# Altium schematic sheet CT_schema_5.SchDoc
size 339 x 183 mm
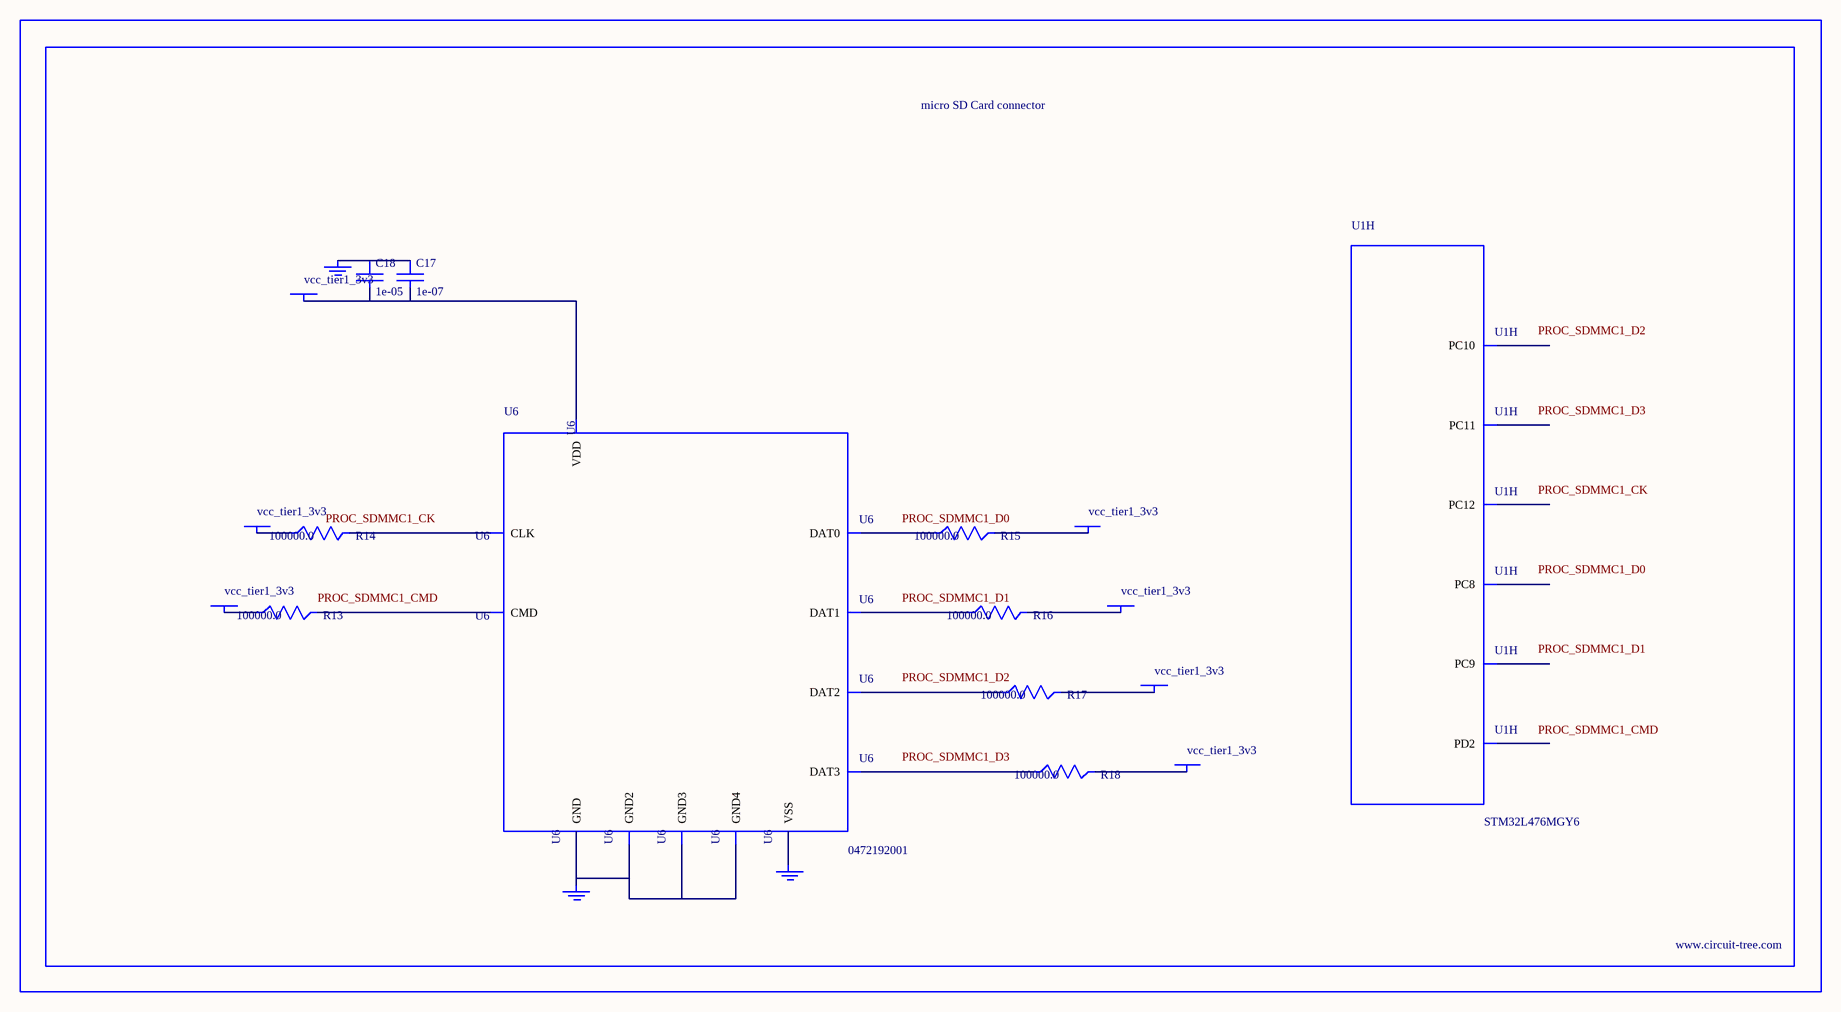
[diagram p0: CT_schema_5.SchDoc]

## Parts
BORDER4  (no value)
C17  1e-07  [C0402]
C18  1e-05  [C0805]
GND_INSTANCE_4_0  (no value)
GND_INSTANCE_4_1  (no value)
GND_INSTANCE_4_2  (no value)
POWER_INSTANCE_4_0  vcc_tier1_3v3
POWER_INSTANCE_4_1  vcc_tier1_3v3
POWER_INSTANCE_4_2  vcc_tier1_3v3
POWER_INSTANCE_4_3  vcc_tier1_3v3
POWER_INSTANCE_4_4  vcc_tier1_3v3
POWER_INSTANCE_4_5  vcc_tier1_3v3
POWER_INSTANCE_4_6  vcc_tier1_3v3
R13  100000.0  [R0603]
R14  100000.0  [R0603]
R15  100000.0  [R0603]
R16  100000.0  [R0603]
R17  100000.0  [R0603]
R18  100000.0  [R0603]
U1  STM32L476MGY6  [WLCSP81]  (part H of 10)
U6  0472192001  [MOLEX_47219-2001]

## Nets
NetC17_1: C17.1 C18.1 GND_INSTANCE_4_0.0(GND)
NetC17_2: C17.2 C18.2 POWER_INSTANCE_4_3.0(PWR) U6.4(VDD)
NetGND_INSTANCE_4_1_0: GND_INSTANCE_4_1.0(GND) U6.6(VSS)
NetGND_INSTANCE_4_2_0: GND_INSTANCE_4_2.0(GND) U6.G1(GND) U6.G2(GND2) U6.G3(GND3) U6.G4(GND4)
NetPOWER_INSTANCE_4_0_0: POWER_INSTANCE_4_0.0(PWR) R17.2
NetPOWER_INSTANCE_4_1_0: POWER_INSTANCE_4_1.0(PWR) R18.2
NetPOWER_INSTANCE_4_2_0: POWER_INSTANCE_4_2.0(PWR) R13.1
NetPOWER_INSTANCE_4_4_0: POWER_INSTANCE_4_4.0(PWR) R14.1
NetPOWER_INSTANCE_4_5_0: POWER_INSTANCE_4_5.0(PWR) R15.2
NetPOWER_INSTANCE_4_6_0: POWER_INSTANCE_4_6.0(PWR) R16.2
NetR13_2: R13.2 U6.3(CMD)
NetR14_2: R14.2 U6.5(CLK)
NetR15_1: R15.1 U6.7(DAT0)
NetR16_1: R16.1 U6.8(DAT1)
NetR17_1: R17.1 U6.1(DAT2)
NetR18_1: R18.1 U6.2(DAT3)

Not connected (* = marked no-connect by the designer): U1 A3(PD2) B3(PC12) C3(PC11) D3(PC10) E1(PC9) F2(PC8)

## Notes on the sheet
- Labels drawn without touching a wire or pin: PROC_SDMMC1_CK, PROC_SDMMC1_CMD, PROC_SDMMC1_D0, PROC_SDMMC1_D1, PROC_SDMMC1_D2, PROC_SDMMC1_D3

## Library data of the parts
BORDER4 = BORDER_PAGE4
C17 = C0402C104K3RACTU
C18 = C0805C106K8RACTU
GND_INSTANCE_4_0-GND_INSTANCE_4_2 = GND
POWER_INSTANCE_4_0-POWER_INSTANCE_4_6 = PWR
R13-R18 = RC0603JR-07100KL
